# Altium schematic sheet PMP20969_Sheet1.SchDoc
size B; Date: Not shown in title block; ApprovedBy: Not shown in title block; CheckedBy: Not shown in title block; Author: Not shown in title block; CompanyName: Not shown in title block; Engineer: Not shown in title block; Organization: Not shown in title block; Address1: Not shown in title block; Address2: Not shown in title block; Address3: Not shown in title block; Address4: Not shown in title block; DocumentNumber: 1; Revision: Use project parameter SCH_Rev; SheetNumber: 1; SheetTotal: 1; PageSetup: Record=PageOptions¦CenterHorizontal=True¦CenterVertical=True¦PrintScale=1.00¦XCorrection=1.00¦YCorrection=1.00¦PrintKind=0¦BorderSize=5000000¦LeftOffset=0¦BottomOffset=0¦Orientation=2¦PaperLength=1000¦PaperWidth=1000¦Scale=100¦PaperSource=15¦PrintQuality=600¦MediaType=1¦DitherType=10¦PaperKind=Letter¦PrintScaleMode=1
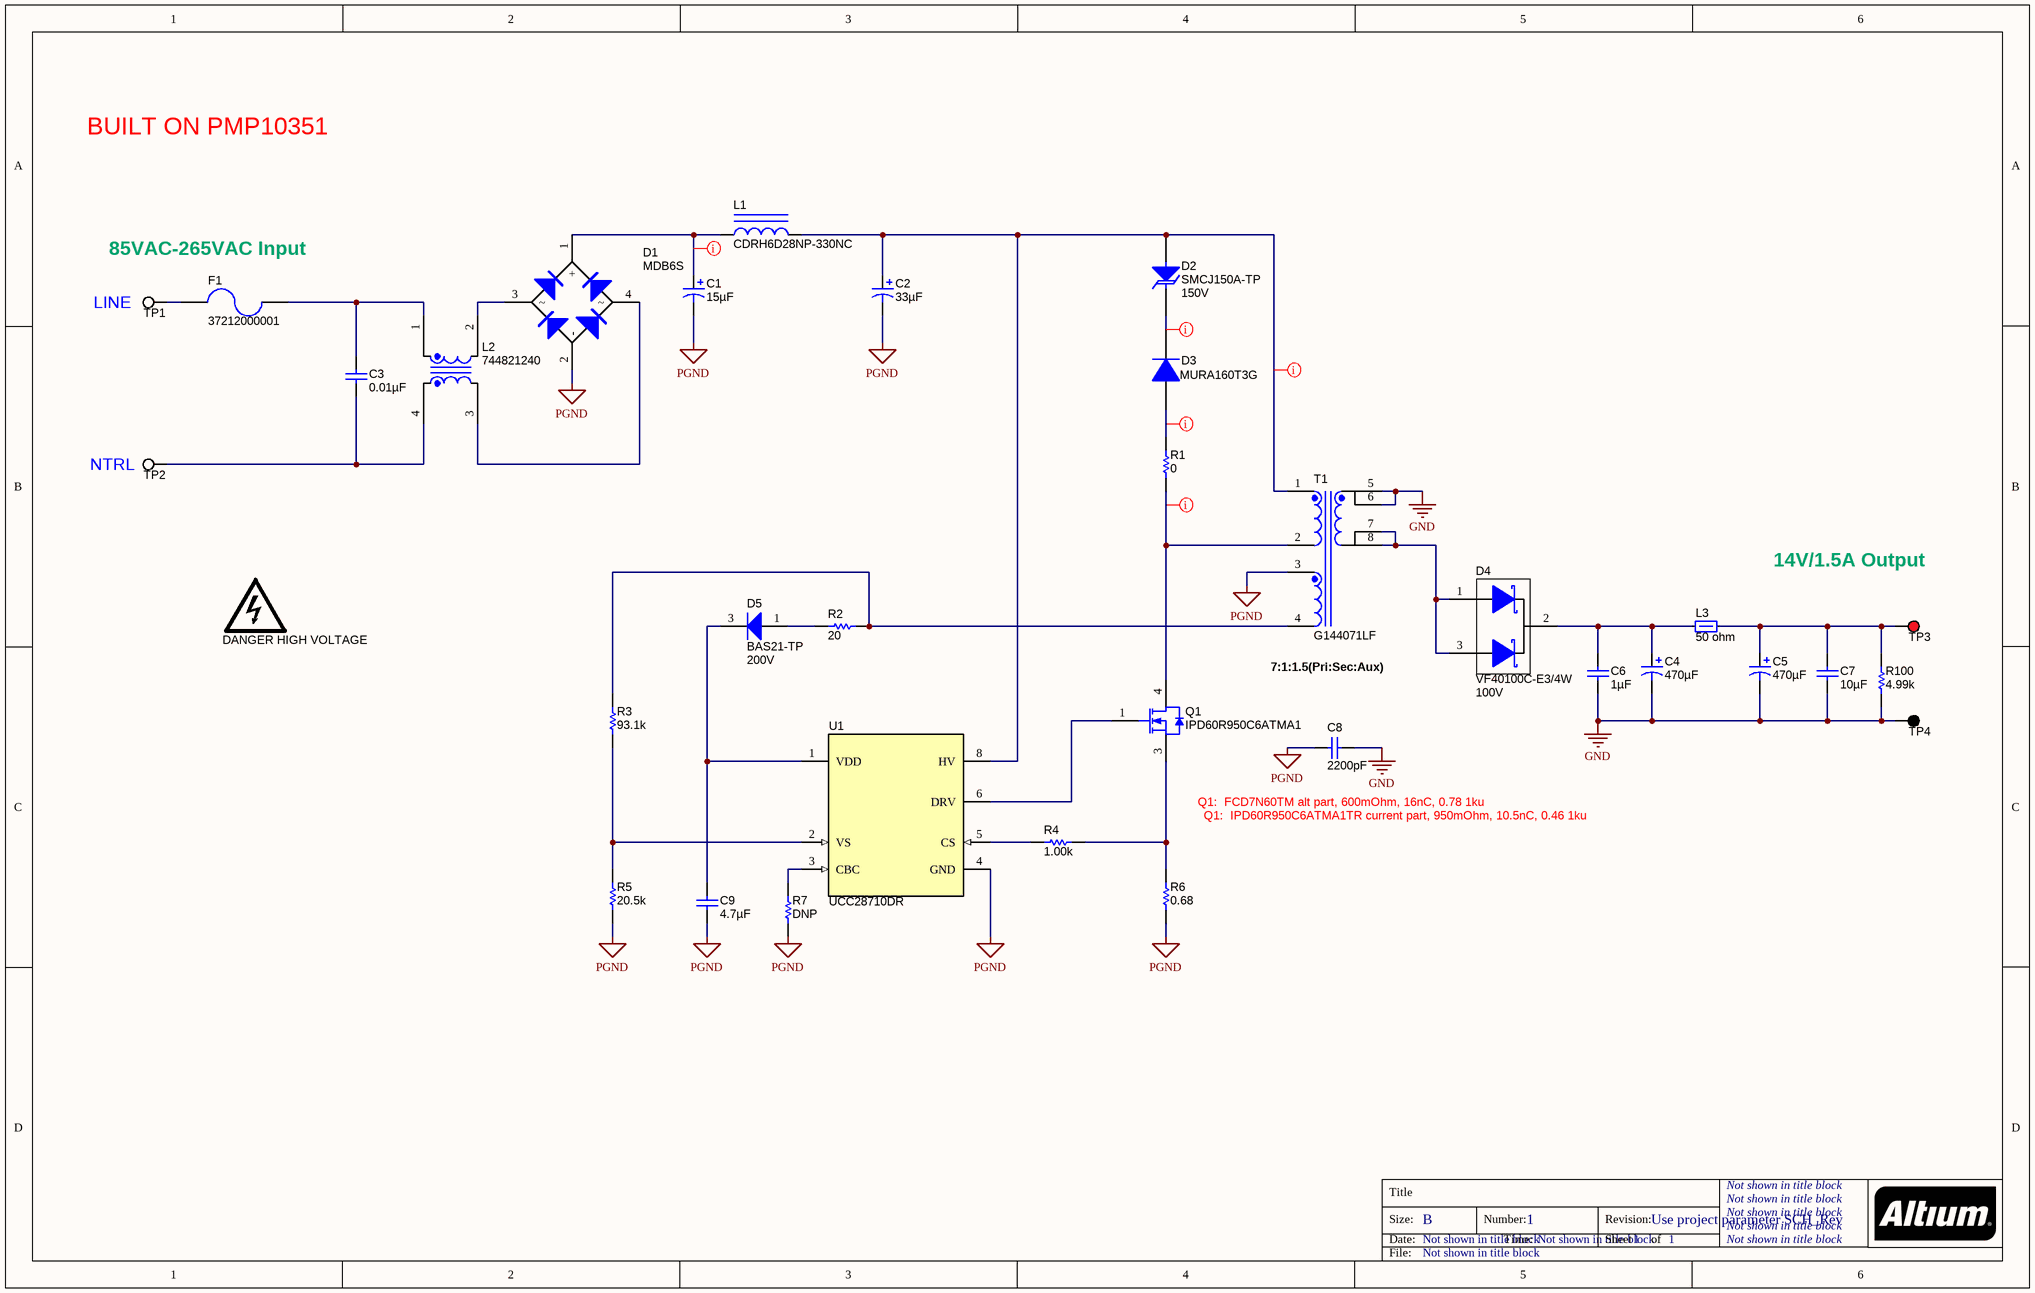
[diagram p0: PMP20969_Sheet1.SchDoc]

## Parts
C1  ValueDisplayed: 15µF  [CAPPR5-12.5X20]  (hidden comment: EEUED2G150)
C2  ValueDisplayed: 33µF  [CAPPR7.5-16X20]  (hidden comment: EEUED2G330S)
C3  ValueDisplayed: 0.01µF  [B32921_9mm]  (hidden comment: B32921C3103K)
C4  ValueDisplayed: 470µF  [ZLG_800x1600]  (hidden comment: 16ZLG470MEFC8X16)
C5  ValueDisplayed: 470µF  [ZLG_800x1600]  (hidden comment: 16ZLG470MEFC8X16)
C6  ValueDisplayed: 1µF  [0603L]  (hidden comment: GRM188R61E105KA12D)
C7  ValueDisplayed: 10µF  [0805L]  (hidden comment: GRM21BR61E106MA73)
C8  ValueDisplayed: 2200pF  [CAPRD500W60D800H850]  (hidden comment: DE2E3KY222MA2BM01)
C9  ValueDisplayed: 4.7µF  [1206L]  (hidden comment: GRM319R61H475KA12)
D1  MDB6S  [MICRODIP_4]
D2  SMCJ150A-TP  value 150V  [SMC]
D3  MURA160T3G  [SMA]
D4  VF40100C-E3/4W  value 100V  [TO-220AB]
D5  BAS21-TP  value 200V  [SOT-23L]
F1  37212000001  [FUSE_372]
L1  CDRH6D28NP-330NC  [CDRH6D28]
L2  744821240  [WE-CMB_XS]
L3  value 50 ohm  [1206L]  (hidden comment: HI1206T500R-10)
LOGO1  DANGER HIGH VOLTAGE  [IEC_HighVoltage_Small]  (no BOM)
Q1  IPD60R950C6ATMA1  [DPAK]
R1  ValueDisplayed: 0  [2010]  (hidden comment: CRCW20100000Z0EF)
R2  ValueDisplayed: 20  [0603L]  (hidden comment: CRCW060320R0JNEA)
R3  ValueDisplayed: 93.1k  [0402]  (hidden comment: CRCW040293K1FKED)
R4  ValueDisplayed: 1.00k  [0402L]  (hidden comment: CRCW04021K00FKED)
R5  ValueDisplayed: 20.5k  [0402]  (hidden comment: CRCW040220K5FKED)
R6  ValueDisplayed: 0.68  [0805_HV]  (hidden comment: ERJ-6RQFR68V)
R7  value DNP  [0603L]  (hidden comment: N/A)
R100  ValueDisplayed: 4.99k  [0402L]  (hidden comment: CRCW04024K99FKED)
T1  G144071LF  [GCI_G144071LF]
TP1  5012  [Keystone5012]  (value not drawn)
TP2  5012  [Keystone5012]  (value not drawn)
TP3  5010  [Keystone5010]  (value not drawn)
TP4  5011  [Keystone5011]  (value not drawn)
U1  UCC28710DR  [D0007A_N]

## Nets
GND: C4.2(-) C5.2(-) C6.2 C7.2 C8.1 R100.2 T1.5 T1.6 TP4.1
PGND: C1.2(-) C2.2(-) C8.2 C9.2 D1.2(-) R5.1 R6.1 R7.1 T1.3 U1.4(GND)
NetC1_1: C1.1(+) D1.1(+) L1.1
NetC2_1: C2.1(+) D2.2(A) L1.2 T1.1 U1.8(HV)
NetC3_1: C3.1 F1.1 L2.1
NetC3_2: C3.2 L2.4 TP2.1
NetC4_1: C4.1(+) C6.1 D4.2(K) L3.1
NetC5_1: C5.1(+) C7.1 L3.2 R100.1 TP3.1
NetC9_1: C9.1 D5.3(K) U1.1(VDD)
NetD1_3: D1.3 L2.2
NetD1_4: D1.4 L2.3
NetD2_1: D2.1(K) D3.1(K)
NetD3_2: D3.2(A) R1.2
NetD4_1: D4.1(A) D4.3(A) T1.7 T1.8
NetD5_1: D5.1(A) R2.2
NetF1_2: F1.2 TP1.1
NetQ1_1: Q1.1(G) U1.6(DRV)
NetQ1_3: Q1.3(S) R4.1 R6.2
NetQ1_4: Q1.4(D) R1.1 T1.2
NetR2_1: R2.1 R3.2 T1.4
NetR3_1: R3.1 R5.2 U1.2(VS)
NetR4_2: R4.2 U1.5(CS)
NetR7_2: R7.2 U1.3(CBC)

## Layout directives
rule Clearance Constraint [Clearance = 24mil]: NetQ1_4
rule Clearance Constraint [Clearance = 25mil]: NetC1_1, NetC2_1, NetD2_1, NetD3_2

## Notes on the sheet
- BUILT ON PMP10351
- (near TP1) LINE
- 85VAC-265VAC Input
- (near TP2) NTRL
- 14V/1.5A Output
- (near T1) 7:1:1.5(Pri:Sec:Aux)
- Q1:  FCD7N60TM alt part, 600mOhm, 16nC, 0.78 1ku
- Q1:  IPD60R950C6ATMA1TR current part, 950mOhm, 10.5nC, 0.46 1ku

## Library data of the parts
C1 = EEUED2G150: CAP, AL, 15uF, 400V, +/-20%, 1.909859 ohm, TH; Manufacturer: Panasonic; Polarized: Y; CompType: Capacitor; U/M: EA; Cap_F: 0.000015; Tolerance_%: 20; VDC_V: 400; IRMS_A: 0.41; TaMin_C: -25; TaMax_C: 105; AC_Derating: 0.3
C2 = EEUED2G330S: CAP, AL, 33 µF, 400 V, +/- 20%, 0.868117 ohm, TH; Manufacturer: Panasonic; Polarized: Y; CompType: Capacitor; Value: 33uF; U/M: EA; Cap_F: 0.000033; Tolerance_%: 20; VDC_V: 400; Value2: 400V; IRMS_A: 0.73; TaMin_C: -25; TaMax_C: 105; AC_Derating: 0.3
C3 = B32921C3103K: CAP, Film, 0.01 µF, 630 V,+/- 10%, TH; Manufacturer: TDK; Polarized: N; CompType: Capacitor; Value: 0.01uF; U/M: EA; Cap_F: 0.00000001; Tolerance_%: 10; Value1: Unknown; VDC_V: 630; Value2: 630V; TaMax_C: 110; SizeAreaWB_mm2: 90; SizeArea_mm2: 52; SizeX_mm: 4; SizeY_mm: 13; SizeZ_mm: 9; AEC Category: Q200
C4 C5 = 16ZLG470MEFC8X16: CAP, AL, 470 µF, 16 V, +/- 20%, 0.028 ohm, TH; Manufacturer: Rubycon; Polarized: Y; CompType: Capacitor; Value: 470uF; U/M: EA; Cap_F: 0.00047; Tolerance_%: 20; VDC_V: 16; Value2: 16V; ESR_ohm: 0.028; IRMS_A: 1.25; TaMin_C: -40; TaMax_C: 105; Cap_Case: 8x16mm
C6 = GRM188R61E105KA12D: CAP, CERM, 1 µF, 25 V, +/- 10%, X5R, 0603; Manufacturer: MuRata; Polarized: N; CompType: Capacitor; Value: 1uF; U/M: EA; Cap_F: 0.000001; Tolerance_%: 10; Value1: Unknown; VDC_V: 25; Value2: 25V; TaMin_C: -55; TaMax_C: 85; Cap_Case: 0603
C7 = GRM21BR61E106MA73: CAP, CERM, 10 µF, 25 V, +/- 20%, X5R, 0805; Manufacturer: MuRata; Polarized: N; CompType: Capacitor; Value: 10uF; U/M: EA; Cap_F: 0.00001; Tolerance_%: 20; Value1: Unknown; VDC_V: 25; Value2: 25V; TaMin_C: -55; TaMax_C: 85; Cap_Case: 0805
C8 = DE2E3KY222MA2BM01: CAP, CERM, 2200pF, 250V, +/-20%, KY, Radial D8x5mm; Manufacturer: MuRata; Polarized: N; CompType: Capacitor; U/M: EA; Cap_F: 0.0000000022; Tolerance_%: 20; Value1: Unknown; VDC_V: 250; TaMin_C: -25; TaMax_C: 85
C9 = GRM319R61H475KA12: CAP, CERM, 4.7 µF, 50 V, +/- 10%, X5R, 1206; Manufacturer: MuRata; Polarized: N; CompType: Capacitor; Value: 4.7uF; U/M: EA; Cap_F: 0.0000047; Tolerance_%: 10; Value1: Unknown; VDC_V: 50; Value2: 50V; TaMin_C: -55; TaMax_C: 85; Cap_Case: 1206
D1 = MDB6S: Diode, Switching-Bridge, 600 V, 1 A, MICRODIP_4; Manufacturer: Fairchild Semiconductor; U/M: EA; Vf_V: 1.1; Value: 600V; Value1: 1A; Value2: 1.1V; Io_A: 1; Vr_V: 600; TJmax_C: 150; SizeAreaWB_mm2: 59.5; SizeArea_mm2: 32.5; SizeX_mm: 6.5; SizeY_mm: 5; SizeZ_mm: 1.45; AEC Category: Q101; Green_Lifecycle: Not Set; Green_REACh: Incomplete
D2 = SMCJ150A-TP: Diode, TVS, Uni, 150 V, 243 Vc, SMC; Manufacturer: Micro Commercial Components; U/M: EA; Vr_V: 150; Value1: W; SizeAreaWB_mm2: 83.2686; SizeArea_mm2: 50.5686; SizeX_mm: 8.13; SizeY_mm: 6.22; SizeZ_mm: 2.6; AEC Category: Q101; AEC Qualified: N
D3 = MURA160T3G: Diode, Ultrafast, 600V, 1A, SMA; Manufacturer: ON Semiconductor; Value: 1.05V; U/M: EA; Vf_V: 1.05; Io_A: 1; Vr_V: 600; TJmax_C: 175
D4 = VF40100C-E3/4W: Diode, Schottky, 100V, 20A, TH; Manufacturer: Vishay-Semiconductor; SymbolCreator: a0411947; U/M: EA; Vf_V: 0.73; Value2: 0.73V; Io_A: 20; Vr_V: 100; TJmax_C: 150; RJC_CperW: 2
D5 = BAS21-TP: Diode, P-N, 200V, 200A, SOT-23; Manufacturer: Micro Commercial Components; U/M: EA; Vf_V: 1.25; Io_A: 200; Value2: 1.25V; TJmax_C: 150; RJC_CperW: 430
F1 = 37215000001: Fuse, 2A, 250V, TH; Manufacturer: Littelfuse; U/M: EA; OpeningTime_100%_min: 4; OpeningTime_200%_max: 2; VDC_V: 250; Irating_A: 5; MeltingTyp: 94; Vdrop: 0.08; Soldering_Wave_MaxTemp_C: 260
L1 = CDRH6D28NP-330NC: Inductor, Shielded Drum Core, Ferrite, 33uH, 0.97A, 0.165 ohm, SMD; Manufacturer: Sumida; Ind_H: 33.0E-6; ValueDisplayed: 33µH; Imax_A: 0.97; Irms: 0.97A @ 30C rise; Isat: 0.97A @ 35% inductance drop; DCR_ohm: 0.165; U/M: EA
L2 = 744821240: Coupled inductor, 4000uH, 1.5A, 0.14 ohm, +/-30%, TH; Manufacturer: Wurth Elektronik eiSos; SymbolCreator: a0412235; Ind_H: 0.004; DCR_Ohm: 0.14; Isat: 1.5; Tolerance_%: 30; U/M: EA
L3 = HI1206T500R-10: Ferrite Bead, 50 ohm @ 100MHz, 6A, 1206; Manufacturer: Laird-Signal Integrity Products; Imax_A: 6; DCR_ohm: 0.01; Value1: 0.01 ohm; ZTyp@100MHz_Ohm: 50; Ztyp@1GHz_Ohm: 70
LOGO1 = IEC_HighVoltage: IEC 61010-1 High Voltage Warning; SymbolCreator: a0412235
Q1 = IPD60R950C6ATMA1: MOSFET, N-CH, 600 V, 4.4 A, DPAK; Manufacturer: Infineon Technologies; Alternate Manufacturer: None; U/M: EA; ChType: N; Value: 600V; VdsMax_V: 600; Value1: ? ohm; Value2: 13 nC; QgTyp_nC: 13; Vgs_V: 20; IdsMax_A: 4.4; SizeAreaWB_mm2: 101.7114; SizeArea_mm2: 64.8114; SizeX_mm: 9.91; SizeY_mm: 6.54; SizeZ_mm: 2.29; AEC Category: Q101
R1 = CRCW20100000Z0EF: RES, 0, 5%, 0.75 W, AEC-Q200 Grade 0, 2010; Manufacturer: Vishay-Dale; CompType: Resistor; Value: 0; Value_Code: 0000; Tolerance_%: 5; Power_W: 0.75; Value2: 0.75W; TempCo: ppm/C; SizeArea_mm2: 12.5; SizeY_mm: 2.5; SizeZ_mm: 1.66; EIA_Code: E24; U/M: EA; AEC Category: Q200; AEC Qualified: Y
R2 = CRCW060320R0JNEA: RES, 20, 5%, 0.1 W, 0603; Manufacturer: Vishay-Dale; CompType: Resistor; Value: 20; Value_Code: 20R0; Tolerance_%: 5; Power_W: 0.1; Value2: 0.1W; VDC_V: 75; TempCo: 200 ppm/C; EIA_Code: E24; U/M: EA
R3 = CRCW040293K1FKED: RES, 93.1 k, 1%, 0.063 W, 0402; Manufacturer: Vishay-Dale; CompType: Resistor; Value: 93.1k; Res_ohm: 93100; Value_Code: 93k1; Tolerance_%: 1; Power_W: 0.063; Value2: 0.063W; VDC_V: 50; TempCo: 100 ppm/C; SizeArea_mm2: 0.5; SizeZ_mm: 0.6; EIA_Code: E96; U/M: EA; AEC Category: Q200
R4 = CRCW04021K00FKED: RES, 1.00 k, 1%, 0.063 W, 0402; Manufacturer: Vishay-Dale; CompType: Resistor; Value: 1.00k; Res_ohm: 1000; Value_Code: 1k00; Tolerance_%: 1; Power_W: 0.063; Value2: 0.063W; VDC_V: 50; TempCo: 100 ppm/C; EIA_Code: E96; U/M: EA
R5 = CRCW040220K5FKED: RES, 20.5 k, 1%, 0.063 W, 0402; Manufacturer: Vishay-Dale; CompType: Resistor; Value: 20.5k; Res_ohm: 20500; Value_Code: 20k5; Tolerance_%: 1; Power_W: 0.063; Value2: 0.063W; VDC_V: 50; TempCo: 100 ppm/C; SizeArea_mm2: 0.5; SizeZ_mm: 0.6; EIA_Code: E96; U/M: EA; AEC Category: Q200
R6 = ERJ-6RQFR68V: RES, 0.68, 1%, 0.125 W, 0805; Manufacturer: Panasonic; CompType: Resistor; Value: 0.68; Value_Code: R680; Tolerance_%: 1; Power_W: 0.125; Value2: 0.125W; TempCo: 250 ppm/C; SizeArea_mm2: 2.5; SizeX_mm: 2; SizeY_mm: 1.25; SizeZ_mm: 1.45; EIA_Code: E96; U/M: EA; AEC Category: Q200; Green_Lifecycle: Not Set; Green_REACh: Incomplete
R7 = CRCW06030000Z0EA: Do Not Populate; CompType: Resistor; Res_ohm: 0; Value_Code: 0000; Tolerance_%: 5; Value1: 5%; Power_W: 0.1; Value2: 0.1W; VDC_V: 75; TempCo: 200 ppm/C; EIA_Code: E24; U/M: EA
R100 = CRCW04024K99FKED: RES, 4.99 k, 1%, 0.063 W, 0402; Manufacturer: Vishay-Dale; CompType: Resistor; Value: 4.99k; Res_ohm: 4990; Value_Code: 4k99; Tolerance_%: 1; Power_W: 0.063; Value2: 0.063W; VDC_V: 50; TempCo: 100 ppm/C; EIA_Code: E96; U/M: EA
T1 = G144071LF: Transformer, 400 uH, TH; Manufacturer: GCI Technologies; SymbolCreator: Altium; DCR_Ohm: 1; Value: 400 uH; LeakageL: 6 uH; U/M: EA
TP1 TP2 = 5012: Test Point, Multipurpose, White, TH; Manufacturer: Keystone; CompType: Test Point Loop; U/M: EA
TP3 = 5010: Test Point, Multipurpose, Red, TH; Manufacturer: Keystone; CompType: Test Point Loop; U/M: EA
TP4 = 5011: Test Point, Multipurpose, Black, TH; Manufacturer: Keystone; CompType: Test Point Loop; U/M: EA
U1 = UCC28710DR: Constant-Voltage, Constant-Current PWM Controller with Primary-Side Regulation, D0007A (SOIC-7); Manufacturer: Texas Instruments; SymbolCreator: a0411947; SizeArea_mm2: 29.4; SizeAreaWB_mm2: 55.2; SizeX_mm: 6; SizeY_mm: 4.9; SizeZ_mm: 1.75; CompType: IC; U/M: EA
